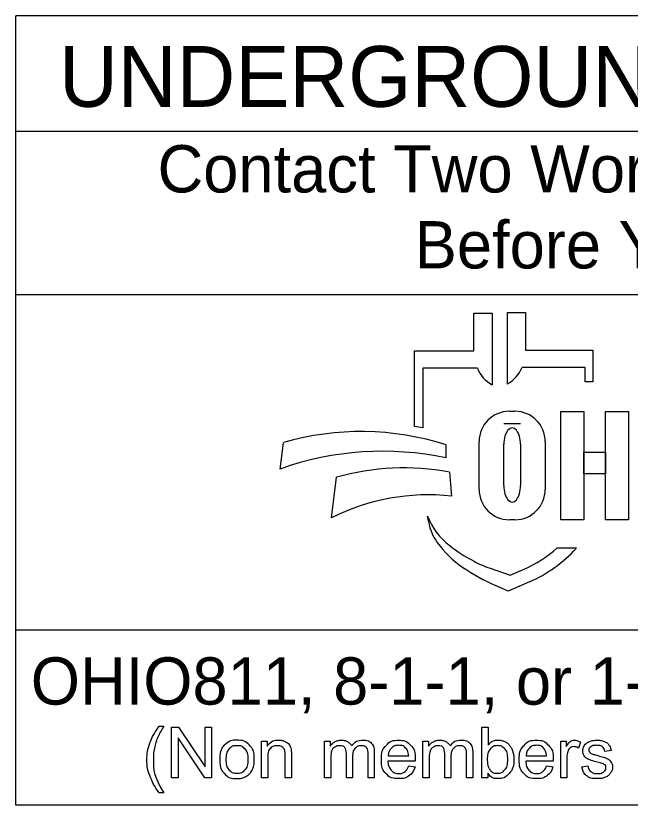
# Model space of a CAD drawing. Extents: x 0 to 34, y 0 to 22.
# Drawn here: x 16.335 to 18.154, y 7.33 to 9.667 of the extents above; entities that cross this region are included whole.
import ezdxf

# ---------------------------------------------------------------- set-up
doc = ezdxf.new("R2010")
doc.units = 0
doc.layers.add('SH_Data', color=7, linetype='Continuous')
doc.layers.add('SH_Text', color=7, linetype='Continuous')

msp = doc.modelspace()

# ---------------------------------------------------------------- linework, layer by layer
at = {"layer": 'SH_Data'}
for p, q in [((16.3351, 7.33), (16.3351, 9.6675)), ((20.5851, 9.6675), (16.3351, 9.6675)), ((16.3351, 9.3259), (20.5851, 9.3259)), ((16.3351, 8.8425), (20.5851, 8.8425)), ((20.5851, 7.8479), (16.3351, 7.8479)), ((20.5851, 7.33), (16.3351, 7.33))]:
    msp.add_line(p, q, dxfattribs=at)
at = {"layer": 'SH_Text'}
for p, q in [((17.7904, 8.5772), (17.7904, 8.7893)), ((17.7904, 8.7893), (17.844, 8.7893)), ((17.844, 8.7893), (17.844, 8.6778)), ((17.6911, 8.6755), (17.6911, 8.787)), ((17.6911, 8.787), (17.7447, 8.787)), ((17.7447, 8.787), (17.7447, 8.5749)), ((17.5151, 8.4516), (17.5151, 8.6755)), ((17.5151, 8.6755), (17.6911, 8.6755)), ((17.844, 8.6778), (18.0433, 8.6778)), ((18.0433, 8.6778), (18.0433, 8.584)), ((18.02, 8.6264), (17.8336, 8.6264)), ((18.02, 8.584), (18.02, 8.6264)), ((17.5404, 8.6241), (17.5404, 8.4472)), ((17.7015, 8.6241), (17.5404, 8.6241)), ((18.0433, 8.584), (18.02, 8.584)), ((17.7961, 8.4963), (17.8126, 8.4963)), ((17.8294, 8.4593), (17.7796, 8.4593)), ((17.1178, 8.3253), (17.1272, 8.4034)), ((17.6084, 8.3969), (17.6084, 8.3581)), ((17.7066, 8.2648), (17.7066, 8.4068)), ((17.7795, 8.2762), (17.7795, 8.3986)), ((17.8293, 8.3986), (17.8293, 8.2762)), ((17.9021, 8.4068), (17.9021, 8.2648)), ((17.2696, 8.1808), (17.2843, 8.3009)), ((17.6184, 8.3163), (17.6246, 8.2454)), ((17.5573, 8.1679), (17.5542, 8.1858)), ((17.8126, 8.1754), (17.7961, 8.1754)), ((17.9376, 8.092), (17.995, 8.092)), ((17.7392, 8.0316), (17.7986, 8.0111)), ((17.7986, 8.0111), (17.8396, 8.0289)), ((17.7926, 7.9641), (17.7552, 7.9806)), ((17.8558, 7.9916), (17.7926, 7.9641))]:
    msp.add_line(p, q, dxfattribs=at)
for points in [[(17.9485, 8.4953), (18.0165, 8.4953), (18.0165, 8.1753), (17.9485, 8.1753)], [(18.0807, 8.4953), (18.1486, 8.4953), (18.1486, 8.1753), (18.0807, 8.1753)], [(18.0165, 8.3754), (18.0807, 8.3754), (18.0807, 8.3114), (18.0165, 8.3114)]]:
    msp.add_lwpolyline(points, close=True, dxfattribs=at)
for points in [[(16.7597, 7.5638), (16.7729, 7.5638)], [(16.7964, 7.4111), (16.7964, 7.5613), (16.8168, 7.5613), (16.8958, 7.4434), (16.8958, 7.5613), (16.9148, 7.5613), (16.9148, 7.4111), (16.8944, 7.4111), (16.8154, 7.5291), (16.8154, 7.4111), (16.7964, 7.4111)], [(17.7319, 7.4111), (17.7148, 7.4111), (17.7148, 7.5613), (17.7333, 7.5613), (17.7333, 7.5078)], [(17.0624, 7.4111), (17.0624, 7.52), (17.079, 7.52), (17.079, 7.5045)], [(17.2488, 7.4111), (17.2488, 7.52), (17.2653, 7.52), (17.2653, 7.5046)], [(17.5402, 7.4111), (17.5402, 7.52), (17.5567, 7.52), (17.5567, 7.5046)], [(17.948, 7.4111), (17.948, 7.52), (17.9646, 7.52), (17.9646, 7.5035)], [(18.007, 7.5165), (18.0006, 7.4994)], [(17.3319, 7.4743), (17.3319, 7.4111), (17.3135, 7.4111), (17.3135, 7.4818)], [(17.3963, 7.4858), (17.3963, 7.4111), (17.3779, 7.4111), (17.3779, 7.4796)], [(17.6233, 7.4743), (17.6233, 7.4111), (17.6048, 7.4111), (17.6048, 7.4818)], [(17.6877, 7.4858), (17.6877, 7.4111), (17.6693, 7.4111), (17.6693, 7.4796)], [(18.097, 7.4918), (18.0789, 7.4894)], [(17.0808, 7.4705), (17.0808, 7.4111), (17.0624, 7.4111)], [(17.1508, 7.478), (17.1508, 7.4111), (17.1323, 7.4111), (17.1323, 7.4773)], [(17.2672, 7.4675), (17.2672, 7.4111), (17.2488, 7.4111)], [(17.5176, 7.4608), (17.4364, 7.4608)], [(17.4374, 7.4759), (17.4982, 7.4759)], [(17.5586, 7.4675), (17.5586, 7.4111), (17.5402, 7.4111)], [(17.9255, 7.4608), (17.8444, 7.4608)], [(17.8454, 7.4759), (17.9062, 7.4759)], [(17.9664, 7.4681), (17.9664, 7.4111), (17.948, 7.4111)], [(17.498, 7.4463), (17.517, 7.4439)], [(17.906, 7.4463), (17.925, 7.4439)], [(18.0106, 7.4436), (18.0288, 7.4465)], [(17.7319, 7.4248), (17.7319, 7.4111)], [(16.7729, 7.367), (16.7597, 7.367)]]:
    msp.add_lwpolyline(points, dxfattribs=at)
for centre, radius, start, end in [((17.7423, 8.6632), 0.0985, 299.2531, 338.0704), ((17.7929, 8.6608), 0.0985, 201.9296, 240.7469), ((17.7961, 8.4068), 0.0895, 90, 180), ((17.8126, 8.4068), 0.0895, 0, 90), ((17.387, 7.6426), 0.8191, 79.2074, 81.0007), ((17.3573, 7.6174), 0.8191, 72.1402, 106.3144), ((17.4203, 7.4863), 0.8919, 77.8238, 109.8274), ((17.4842, 7.5966), 0.7322, 79.44, 105.8467), ((17.7961, 8.2648), 0.0895, 180, 270), ((17.8126, 8.2648), 0.0895, 270, 0), ((17.5563, 7.6134), 0.6357, 83.8248, 116.8021), ((17.7416, 8.2579), 0.2008, 201.0457, 232.5314), ((17.6986, 8.192), 0.1433, 189.6817, 216.0884), ((17.8323, 8.2894), 0.3088, 216.0884, 235.7167), ((17.9342, 8.5091), 0.5173, 232.5314, 241.794), ((17.6962, 8.3594), 0.3602, 293.4582, 312.0712), ((17.6962, 8.3594), 0.401, 293.4582, 317.8286), ((17.849, 8.3503), 0.3371, 241.794, 250.9821), ((17.9988, 8.5337), 0.6044, 235.7167, 246.2325)]:
    msp.add_arc(centre, radius, start, end, dxfattribs=at)
for centre, start_param, end_param in [((17.8044, 8.3986), 4.712389, 7.853982), ((17.8044, 8.2762), 1.570796, 4.712389)]:
    msp.add_ellipse(centre, major_axis=(0, 0.0484), ratio=0.514403, start_param=start_param, end_param=end_param, dxfattribs=at)
for points in [[(16.7597, 7.367), (16.7444, 7.3862), (16.7339, 7.412), (16.7233, 7.4378), (16.7233, 7.4655), (16.7233, 7.4899), (16.7312, 7.5122), (16.7404, 7.5381), (16.7597, 7.5638)], [(16.7729, 7.5638), (16.7605, 7.5425), (16.7565, 7.5334), (16.7503, 7.5192), (16.7467, 7.5039), (16.7423, 7.4847), (16.7423, 7.4654), (16.7423, 7.4161), (16.7729, 7.367)], [(16.9389, 7.4655), (16.9389, 7.4957), (16.9557, 7.5103), (16.9697, 7.5224), (16.9899, 7.5224), (17.0123, 7.5224), (17.0265, 7.5077), (17.0408, 7.493), (17.0408, 7.4671), (17.0408, 7.4461), (17.0345, 7.4341), (17.0282, 7.422), (17.0162, 7.4154), (17.0041, 7.4087), (16.9899, 7.4087), (16.9671, 7.4087), (16.953, 7.4234), (16.9389, 7.438), (16.9389, 7.4655)], [(16.9579, 7.4655), (16.9579, 7.4446), (16.967, 7.4342), (16.9761, 7.4238), (16.9899, 7.4238), (17.0036, 7.4238), (17.0127, 7.4343), (17.0218, 7.4447), (17.0218, 7.4662), (17.0218, 7.4863), (17.0126, 7.4967), (17.0035, 7.5071), (16.9899, 7.5071), (16.9761, 7.5071), (16.967, 7.4968), (16.9579, 7.4864), (16.9579, 7.4655)], [(17.079, 7.5045), (17.091, 7.5224), (17.1136, 7.5224), (17.1234, 7.5224), (17.1317, 7.5188), (17.1399, 7.5153), (17.144, 7.5096), (17.1481, 7.5038), (17.1497, 7.4959), (17.1508, 7.4908), (17.1508, 7.478)], [(17.1323, 7.4773), (17.1323, 7.4885), (17.1302, 7.4941), (17.128, 7.4997), (17.1225, 7.503), (17.1171, 7.5063), (17.1097, 7.5063), (17.0979, 7.5063), (17.0894, 7.4989), (17.0808, 7.4914), (17.0808, 7.4705)], [(17.2653, 7.5046), (17.2704, 7.5126), (17.2789, 7.5175), (17.2874, 7.5224), (17.2983, 7.5224), (17.3104, 7.5224), (17.3181, 7.5173), (17.3259, 7.5123), (17.329, 7.5033), (17.342, 7.5224), (17.3627, 7.5224), (17.3789, 7.5224), (17.3876, 7.5134), (17.3963, 7.5044), (17.3963, 7.4858)], [(17.3135, 7.4818), (17.3135, 7.4941), (17.309, 7.5002), (17.3044, 7.5063), (17.2942, 7.5063), (17.2864, 7.5063), (17.2798, 7.5023), (17.2732, 7.4982), (17.2702, 7.4903), (17.2672, 7.4824), (17.2672, 7.4675)], [(17.3779, 7.4796), (17.3779, 7.4907), (17.3761, 7.4955), (17.3743, 7.5004), (17.3696, 7.5034), (17.3649, 7.5063), (17.3585, 7.5063), (17.3471, 7.5063), (17.3395, 7.4987), (17.3319, 7.4911), (17.3319, 7.4743)], [(17.517, 7.4439), (17.5125, 7.4272), (17.5003, 7.4179), (17.4882, 7.4087), (17.4692, 7.4087), (17.4454, 7.4087), (17.4314, 7.4234), (17.4174, 7.4381), (17.4174, 7.4646), (17.4174, 7.4921), (17.4315, 7.5072), (17.4457, 7.5224), (17.4682, 7.5224), (17.49, 7.5224), (17.5038, 7.5075), (17.5177, 7.4927), (17.5177, 7.4657), (17.5177, 7.4641), (17.5176, 7.4608)], [(17.4982, 7.4759), (17.497, 7.4897), (17.4912, 7.4966), (17.4824, 7.5073), (17.4684, 7.5073), (17.4557, 7.5073), (17.447, 7.4987), (17.4384, 7.4902), (17.4374, 7.4759)], [(17.5567, 7.5046), (17.5618, 7.5126), (17.5703, 7.5175), (17.5788, 7.5224), (17.5897, 7.5224), (17.6018, 7.5224), (17.6095, 7.5173), (17.6172, 7.5123), (17.6204, 7.5033), (17.6333, 7.5224), (17.654, 7.5224), (17.6703, 7.5224), (17.679, 7.5134), (17.6877, 7.5044), (17.6877, 7.4858)], [(17.6048, 7.4818), (17.6048, 7.4941), (17.6003, 7.5002), (17.5958, 7.5063), (17.5856, 7.5063), (17.5778, 7.5063), (17.5712, 7.5023), (17.5646, 7.4982), (17.5616, 7.4903), (17.5586, 7.4824), (17.5586, 7.4675)], [(17.6693, 7.4796), (17.6693, 7.4907), (17.6675, 7.4955), (17.6657, 7.5004), (17.661, 7.5034), (17.6563, 7.5063), (17.6499, 7.5063), (17.6384, 7.5063), (17.6309, 7.4987), (17.6233, 7.4911), (17.6233, 7.4743)], [(17.7317, 7.4664), (17.7317, 7.4468), (17.737, 7.4381), (17.7457, 7.4238), (17.7605, 7.4238), (17.7726, 7.4238), (17.7814, 7.4343), (17.7901, 7.4448), (17.7901, 7.4656), (17.7901, 7.487), (17.7817, 7.4971), (17.7733, 7.5073), (17.7613, 7.5073), (17.7493, 7.5073), (17.7405, 7.4968), (17.7317, 7.4862), (17.7317, 7.4664)], [(17.7333, 7.5078), (17.7449, 7.5224), (17.7631, 7.5224), (17.7731, 7.5224), (17.7821, 7.5183), (17.791, 7.5143), (17.7968, 7.507), (17.8026, 7.4996), (17.8059, 7.4893), (17.8091, 7.479), (17.8091, 7.4672), (17.8091, 7.4392), (17.7953, 7.424), (17.7815, 7.4087), (17.7621, 7.4087), (17.7429, 7.4087), (17.7319, 7.4248)], [(17.925, 7.4439), (17.9205, 7.4272), (17.9083, 7.4179), (17.8962, 7.4087), (17.8772, 7.4087), (17.8534, 7.4087), (17.8394, 7.4234), (17.8254, 7.4381), (17.8254, 7.4646), (17.8254, 7.4921), (17.8395, 7.5072), (17.8537, 7.5224), (17.8762, 7.5224), (17.898, 7.5224), (17.9118, 7.5075), (17.9256, 7.4927), (17.9256, 7.4657), (17.9256, 7.4641), (17.9255, 7.4608)], [(17.9062, 7.4759), (17.905, 7.4897), (17.8992, 7.4966), (17.8904, 7.5073), (17.8764, 7.5073), (17.8637, 7.5073), (17.855, 7.4987), (17.8463, 7.4902), (17.8454, 7.4759)], [(17.9646, 7.5035), (17.9709, 7.515), (17.9763, 7.5187), (17.9816, 7.5224), (17.9881, 7.5224), (17.9974, 7.5224), (18.007, 7.5165)], [(18.0789, 7.4894), (18.0777, 7.4978), (18.0718, 7.5025), (18.0659, 7.5073), (18.0551, 7.5073), (18.0424, 7.5073), (18.0369, 7.5031), (18.0315, 7.4988), (18.0315, 7.4932), (18.0315, 7.4896), (18.0338, 7.4867), (18.036, 7.4838), (18.0408, 7.4818), (18.0436, 7.4808), (18.0571, 7.4771), (18.0767, 7.4719), (18.0845, 7.4685), (18.0923, 7.4652), (18.0967, 7.4589), (18.1011, 7.4525), (18.1011, 7.4431), (18.1011, 7.4339), (18.0957, 7.4258), (18.0903, 7.4176), (18.0802, 7.4132), (18.07, 7.4087), (18.0572, 7.4087), (18.0359, 7.4087), (18.0248, 7.4175), (18.0136, 7.4263), (18.0106, 7.4436)], [(18.0288, 7.4465), (18.0303, 7.4355), (18.0373, 7.4297), (18.0444, 7.4238), (18.057, 7.4238), (18.0698, 7.4238), (18.0759, 7.429), (18.0821, 7.4342), (18.0821, 7.4412), (18.0821, 7.4474), (18.0766, 7.451), (18.0728, 7.4535), (18.0578, 7.4573), (18.0375, 7.4624), (18.0296, 7.4661), (18.0218, 7.4699), (18.0177, 7.4765), (18.0137, 7.4831), (18.0137, 7.491), (18.0137, 7.4983), (18.017, 7.5045), (18.0203, 7.5107), (18.0261, 7.5148), (18.0304, 7.518), (18.0378, 7.5202), (18.0453, 7.5224), (18.0538, 7.5224), (18.0666, 7.5224), (18.0763, 7.5187), (18.086, 7.515), (18.0906, 7.5087), (18.0952, 7.5024), (18.097, 7.4918)], [(18.0006, 7.4994), (17.9938, 7.5034), (17.9871, 7.5034), (17.9811, 7.5034), (17.9763, 7.4997), (17.9715, 7.4961), (17.9695, 7.4896), (17.9664, 7.4798), (17.9664, 7.4681)], [(17.4364, 7.4608), (17.4374, 7.4429), (17.4465, 7.4334), (17.4557, 7.4238), (17.4693, 7.4238), (17.4794, 7.4238), (17.4866, 7.4292), (17.4938, 7.4345), (17.498, 7.4463)], [(17.8444, 7.4608), (17.8454, 7.4429), (17.8545, 7.4334), (17.8637, 7.4238), (17.8773, 7.4238), (17.8874, 7.4238), (17.8946, 7.4292), (17.9018, 7.4345), (17.906, 7.4463)]]:
    msp.add_open_spline(points, degree=3, dxfattribs=at)

# ---------------------------------------------------------------- texts
for s, height, p in [('UNDERGROUND UTILITIES', 0.18, (16.4632, 9.3979)), ('Contact Two Working Days', 0.14, (16.7547, 9.1444)), ('Before You Dig', 0.14, (17.5159, 8.9194)), ('OHIO811, 8-1-1, or 1-800-362-2764', 0.14, (16.3795, 7.6278))]:
    msp.add_text(s, height=height, dxfattribs=at).set_placement(p)

doc.saveas('drawing.dxf')
